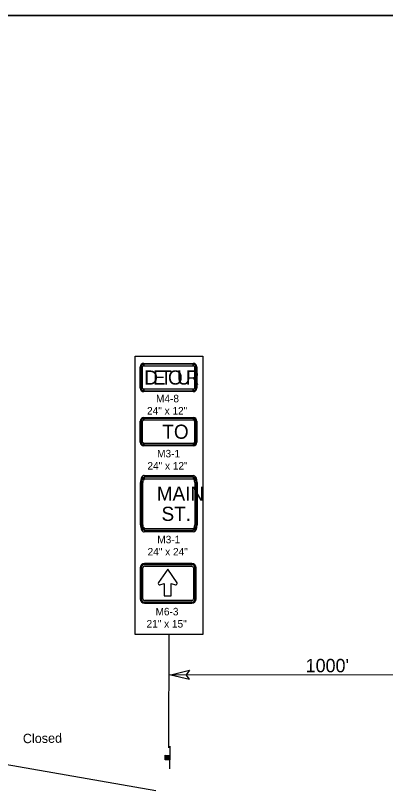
# Model space of a CAD drawing. Extents: x 10133 to 81668, y 6132 to 11018.
# Drawn here: x 11999 to 12392, y 9117 to 9944 of the extents above; entities that cross this region are included whole.
import ezdxf

# ---------------------------------------------------------------- set-up
doc = ezdxf.new("R2010")
doc.units = 0
for name, color, linetype in [('dsnTextFinalPlan', 7, 'Continuous'), ('Level 10', 7, 'Continuous'), ('Level 2', 7, 'Continuous'), ('Level 5', 7, 'Continuous'), ('SheetBorder', 7, 'Continuous'), ('SheetText', 7, 'Continuous')]:
    doc.layers.add(name, color=color, linetype=linetype)

msp = doc.modelspace()

# ---------------------------------------------------------------- linework, layer by layer
at = {"layer": 'dsnTextFinalPlan'}
for p, q in [((12162.2, 9164.8), (12162.5, 9285.33)), ((12536.02, 9241.73), (12162.39, 9242.64)), ((12163.21, 9142.47), (12163.54, 9166.47)), ((11931.03, 9157.44), (12148.4, 9119.44)), ((12158.69, 9152.01), (12158.76, 9156.89)), ((12159.04, 9156.88), (12158.97, 9152.01)), ((12159.17, 9152), (12159.23, 9156.88)), ((12159.51, 9156.88), (12159.44, 9152)), ((12159.64, 9152), (12159.69, 9156.87)), ((12160.07, 9156.87), (12160.02, 9151.99)), ((12160.2, 9151.99), (12160.26, 9156.86)), ((12160.64, 9156.86), (12160.57, 9151.98)), ((12160.9, 9151.98), (12160.97, 9156.86)), ((12161.25, 9156.85), (12161.2, 9151.97)), ((12161.38, 9151.97), (12161.44, 9156.85)), ((12161.67, 9156.85), (12161.61, 9151.97)), ((12161.9, 9151.97), (12161.97, 9156.84)), ((12162.15, 9156.84), (12162.08, 9151.96)), ((12162.28, 9151.96), (12162.34, 9156.84)), ((12162.57, 9156.83), (12162.51, 9151.96)), ((12162.73, 9151.95), (12162.8, 9156.83)), ((12163.05, 9156.83), (12162.98, 9151.95))]:
    msp.add_line(p, q, dxfattribs=at)
for points in [[(12126.46, 9581.43), (12198.53, 9581.43), (12198.53, 9285.33), (12126.46, 9285.33)], [(12126.46, 9581.43), (12198.53, 9581.43), (12198.53, 9285.33), (12126.46, 9285.33)], [(12163.32, 9156.82), (12163.26, 9151.91), (12158.35, 9151.98), (12158.42, 9156.89)]]:
    msp.add_lwpolyline(points, close=True, dxfattribs=at)
for points in [[(12164.46, 9242.63), (12184.1, 9247.43), (12180.84, 9242.59)], [(12164.46, 9242.63), (12184.07, 9237.73), (12180.84, 9242.59)]]:
    msp.add_lwpolyline(points, dxfattribs=at)
at = {"layer": 'Level 10'}
for p, q in [((12135.67, 9573.92), (12188.28, 9573.92)), ((12131.91, 9547.61), (12131.91, 9570.16)), ((12132.85, 9570.16), (12134.42, 9570.16)), ((12135.67, 9571.41), (12135.67, 9572.98)), ((12188.28, 9572.98), (12188.28, 9571.41)), ((12189.54, 9570.16), (12191.1, 9570.16)), ((12192.04, 9570.16), (12192.04, 9547.61)), ((12134.42, 9547.61), (12132.85, 9547.61)), ((12135.67, 9544.79), (12135.67, 9546.36)), ((12188.28, 9543.85), (12135.67, 9543.85)), ((12188.28, 9546.36), (12188.28, 9544.79)), ((12191.1, 9547.61), (12189.54, 9547.61)), ((12135.72, 9516.23), (12188.33, 9516.23)), ((12135.72, 9513.73), (12135.72, 9515.29)), ((12188.33, 9515.29), (12188.33, 9513.73)), ((12131.96, 9489.92), (12131.96, 9512.47)), ((12132.9, 9512.47), (12134.46, 9512.47)), ((12189.58, 9512.47), (12191.15, 9512.47)), ((12192.09, 9512.47), (12192.09, 9489.92)), ((12134.46, 9489.92), (12132.9, 9489.92)), ((12135.72, 9487.11), (12135.72, 9488.67)), ((12188.33, 9486.17), (12135.72, 9486.17)), ((12188.33, 9488.67), (12188.33, 9487.11)), ((12191.15, 9489.92), (12189.58, 9489.92)), ((12135.91, 9454.65), (12188.52, 9454.65)), ((12135.91, 9449.64), (12135.91, 9452.77)), ((12188.52, 9452.77), (12188.52, 9451.2)), ((12132.15, 9402.03), (12132.15, 9447.13)), ((12133.09, 9447.13), (12134.65, 9447.13)), ((12189.77, 9447.13), (12191.34, 9447.13)), ((12192.28, 9447.13), (12192.28, 9402.03)), ((12134.65, 9402.03), (12133.09, 9402.03)), ((12135.91, 9396.4), (12135.91, 9399.53)), ((12191.34, 9402.03), (12189.77, 9402.03)), ((12188.52, 9394.52), (12135.91, 9394.52)), ((12188.52, 9397.96), (12188.52, 9396.4)), ((12186.63, 9361.01), (12136.46, 9361.01)), ((12136.47, 9359.89), (12186.64, 9359.89)), ((12136.47, 9358.19), (12186.64, 9358.19)), ((12131.95, 9356.5), (12131.95, 9323.24)), ((12133.09, 9323.24), (12133.09, 9356.5)), ((12134.78, 9323.24), (12134.78, 9356.5)), ((12161.03, 9354.93), (12151.11, 9340.66)), ((12171.12, 9340.48), (12161.03, 9354.93)), ((12188.33, 9356.5), (12188.33, 9323.24)), ((12190.02, 9356.5), (12190.02, 9323.24)), ((12191.14, 9323.24), (12191.14, 9356.5)), ((12152.85, 9338.4), (12157.2, 9339.79)), ((12157.2, 9339.79), (12157.2, 9326.74)), ((12164.86, 9339.61), (12164.86, 9339.79)), ((12164.86, 9339.79), (12169.38, 9338.4)), ((12164.86, 9326.56), (12164.86, 9339.61)), ((12157.2, 9326.74), (12157.2, 9326.56)), ((12157.2, 9326.56), (12164.86, 9326.56)), ((12136.46, 9318.74), (12186.63, 9318.74)), ((12186.64, 9321.55), (12136.47, 9321.55)), ((12186.64, 9319.86), (12136.47, 9319.86))]:
    msp.add_line(p, q, dxfattribs=at)
for points in [[(12132.85, 9570.16), (12132.85, 9547.61), (12134.42, 9547.61), (12134.42, 9570.16), (12132.85, 9570.16)], [(12188.28, 9572.98), (12135.67, 9572.98), (12135.67, 9571.41), (12188.28, 9571.41), (12188.28, 9572.98)], [(12191.1, 9547.61), (12191.1, 9570.16), (12189.54, 9570.16), (12189.54, 9547.61), (12191.1, 9547.61)], [(12135.67, 9544.79), (12188.28, 9544.79), (12188.28, 9546.36), (12135.67, 9546.36), (12135.67, 9544.79)], [(12188.33, 9515.29), (12135.72, 9515.29), (12135.72, 9513.73), (12188.33, 9513.73), (12188.33, 9515.29)], [(12132.9, 9512.47), (12132.9, 9489.92), (12134.46, 9489.92), (12134.46, 9512.47), (12132.9, 9512.47)], [(12191.15, 9489.92), (12191.15, 9512.47), (12189.58, 9512.47), (12189.58, 9489.92), (12191.15, 9489.92)], [(12135.72, 9487.11), (12188.33, 9487.11), (12188.33, 9488.67), (12135.72, 9488.67), (12135.72, 9487.11)], [(12188.52, 9452.77), (12135.91, 9452.77), (12135.91, 9451.2), (12188.52, 9451.2), (12188.52, 9452.77)], [(12133.09, 9447.13), (12133.09, 9402.03), (12134.65, 9402.03), (12134.65, 9447.13), (12133.09, 9447.13)], [(12191.34, 9402.03), (12191.34, 9447.13), (12189.77, 9447.13), (12189.77, 9402.03), (12191.34, 9402.03)], [(12135.91, 9396.4), (12188.52, 9396.4), (12188.52, 9397.96), (12135.91, 9397.96), (12135.91, 9396.4)]]:
    msp.add_lwpolyline(points, close=True, dxfattribs=at)
for centre, radius, start, end in [((12135.67, 9570.16), 3.76, 90, 180), ((12188.28, 9570.16), 3.76, 0, 90), ((12135.67, 9570.16), 2.82, 90.00021, 179.99985), ((12135.67, 9570.16), 1.25, 90.00021, 179.99985), ((12188.28, 9570.16), 2.82, 0, 90.00021), ((12188.28, 9570.16), 1.25, 0, 90.00021), ((12135.67, 9547.61), 3.76, 180, 270), ((12135.67, 9547.61), 2.82, 179.99985, 270.00006), ((12135.67, 9547.61), 1.25, 179.99985, 270.00006), ((12188.28, 9547.61), 2.82, 270.00006, 0.00027), ((12188.28, 9547.61), 1.25, 270.00006, 0.00027), ((12188.28, 9547.61), 3.76, 270, 359.99112), ((12135.72, 9512.47), 3.76, 90, 180), ((12135.72, 9512.47), 2.82, 90.00021, 179.99985), ((12188.33, 9512.47), 3.76, 0, 90), ((12188.33, 9512.47), 2.82, 0, 90.00021), ((12135.72, 9512.47), 1.25, 90.00021, 179.99985), ((12188.33, 9512.47), 1.25, 0, 90.00021), ((12135.72, 9489.92), 3.76, 180, 270), ((12135.72, 9489.92), 2.82, 179.99985, 270.00006), ((12135.72, 9489.92), 1.25, 179.99985, 270.00006), ((12188.33, 9489.92), 2.82, 270.00006, 0.00027), ((12188.33, 9489.92), 1.25, 270.00006, 0.00027), ((12188.33, 9489.92), 3.76, 270, 359.99112), ((12136.46, 9356.5), 4.51, 90, 180), ((12136.47, 9356.5), 3.38, 90, 180), ((12136.47, 9356.5), 1.69, 90, 180), ((12186.63, 9356.5), 4.51, 360, 90), ((12186.64, 9356.5), 3.38, 0, 90), ((12186.64, 9356.5), 1.69, 0, 90), ((12152.32, 9339.79), 1.49, 144.26784, 290.86935), ((12169.77, 9339.84), 1.5, 254.96957, 25.41929), ((12136.46, 9323.24), 4.51, 180, 270), ((12136.47, 9323.24), 3.38, 180, 270), ((12136.47, 9323.24), 1.69, 180, 270), ((12186.63, 9323.24), 4.51, 270, 0), ((12186.64, 9323.24), 3.38, 270, 0), ((12186.64, 9323.24), 1.69, 270, 0)]:
    msp.add_arc(centre, radius, start, end, dxfattribs=at)
for centre, major_axis, ratio, start_param, end_param in [((12135.91, 9447.13), (0, 7.52), 0.5, 6.283185, 7.853982), ((12135.91, 9447.13), (0, 5.64), 0.5, 0.000004, 1.570794), ((12135.91, 9447.13), (0, 4.07), 0.307692, 0.000004, 1.570794), ((12188.52, 9447.13), (0, 7.52), 0.5, 4.712389, 6.283185), ((12188.52, 9447.13), (0, 5.64), 0.5, 4.712389, 6.283189), ((12188.52, 9447.13), (0, 4.07), 0.307692, 4.712389, 6.283189), ((12135.91, 9402.03), (0, 7.52), 0.5, 1.570796, 3.141593), ((12135.91, 9402.03), (0, 5.64), 0.5, 1.570794, 3.141594), ((12135.91, 9402.03), (0, 4.07), 0.307692, 1.570794, 3.141594), ((12188.52, 9402.03), (0, 5.64), 0.5, 3.141594, 4.712394), ((12188.52, 9402.03), (0, 4.07), 0.307692, 3.141594, 4.712394), ((12188.52, 9402.03), (0, 7.52), 0.5, 3.141593, 4.712234)]:
    msp.add_ellipse(centre, major_axis=major_axis, ratio=ratio, start_param=start_param, end_param=end_param, dxfattribs=at)
at = {"layer": 'SheetBorder'}
msp.add_lwpolyline([(10132.52, 9944.02), (13267.53, 9944.02), (13267.53, 7924.02), (10132.52, 7924.02)], close=True, dxfattribs=at)
at = {"layer": 'SheetText'}
msp.add_lwpolyline([(10132.52, 9944.02), (10132.52, 7924.02), (13267.53, 7924.02), (13267.53, 9944.02)], close=True, dxfattribs=at)

# ---------------------------------------------------------------- texts
at = {"layer": 'dsnTextFinalPlan'}
msp.add_text("1000'", height=14.238, rotation=359.86134, dxfattribs=at).set_placement((12307.62, 9245.29))
at = {"layer": 'Level 10'}
for s, height, p in [('D', 15.03, (12136.16, 9551.37)), ('E', 15.03, (12145.39, 9551.37)), ('T', 15.03, (12153.17, 9551.37)), ('O', 15.03, (12161.38, 9551.37)), ('U', 15.03, (12170.97, 9551.37)), ('R', 15.03, (12180.21, 9551.37)), ('TO', 15.032, (12155.38, 9493.68)), ('MAIN', 15.032, (12149.47, 9427.83)), ('ST.', 15.032, (12154.53, 9406.3))]:
    msp.add_text(s, height=height, dxfattribs=at).set_placement(p)
at = {"layer": 'Level 2'}
msp.add_text('Closed', height=10, rotation=0.74206, dxfattribs=at).set_placement((12007.22, 9169.73))
at = {"layer": 'Level 5'}
for s, p in [('M4-8', (12148.68, 9532.47)), ('24" x 12"', (12139.13, 9519.47)), ('M3-1', (12149.84, 9473.87)), ('24" x 12"', (12139.51, 9460.87)), ('M3-1', (12150.03, 9382.48)), ('24" x 24"', (12139.7, 9369.48)), ('M6-3', (12148.14, 9305.78)), ('21" x 15"', (12138.58, 9292.78))]:
    msp.add_text(s, height=8, dxfattribs=at).set_placement(p)

doc.saveas('drawing.dxf')
